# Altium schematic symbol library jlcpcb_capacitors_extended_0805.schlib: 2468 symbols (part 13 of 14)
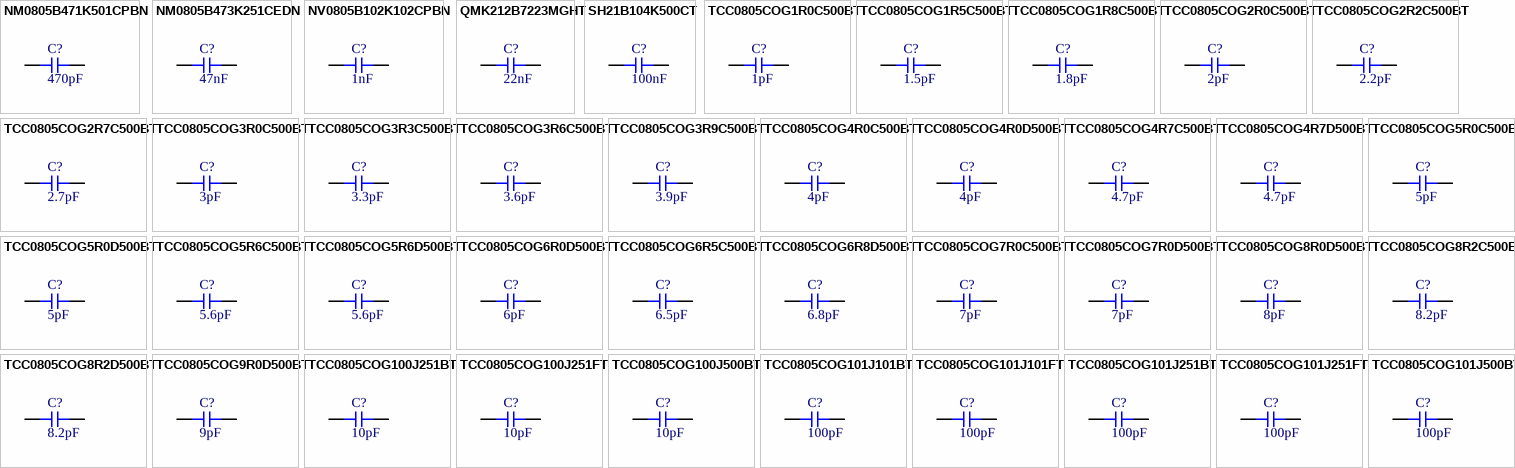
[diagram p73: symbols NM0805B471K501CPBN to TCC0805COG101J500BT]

## TCC0805COG9R0D500BT
designator C?  Capacitance: 9pF  (hidden comment: *)
Capacitor, Ceramic (MLCC), 9pF, ±0.5pF, 50V, C0G, ±0.5pF, SMD 0805; Manufacturer: CCTC; Manufacturer Part Number: TCC0805COG9R0D500BT
footprint CAP-0805 (0805 (2012M) Capacitor)
pins: 1, 2

## TCC0805COG100J251BT
designator C?  Capacitance: 10pF  (hidden comment: *)
Capacitor, Ceramic (MLCC), 10pF, ±5%, 250V, C0G, ±5%, SMD 0805; Manufacturer: CCTC; Manufacturer Part Number: TCC0805COG100J251BT
footprint CAP-0805 (0805 (2012M) Capacitor)
pins: 1, 2

## TCC0805COG100J251FT
designator C?  Capacitance: 10pF  (hidden comment: *)
Capacitor, Ceramic (MLCC), 10pF, ±5%, 250V, C0G, ±5%, SMD 0805; Manufacturer: CCTC; Manufacturer Part Number: TCC0805COG100J251FT
footprint CAP-0805 (0805 (2012M) Capacitor)
pins: 1, 2

## TCC0805COG100J500BT
designator C?  Capacitance: 10pF  (hidden comment: *)
Capacitor, Ceramic (MLCC), 10pF, ±5%, 50V, C0G, ±5%, SMD 0805; Manufacturer: CCTC; Manufacturer Part Number: TCC0805COG100J500BT
footprint CAP-0805 (0805 (2012M) Capacitor)
pins: 1, 2

## TCC0805COG101J101BT
designator C?  Capacitance: 100pF  (hidden comment: *)
Capacitor, Ceramic (MLCC), 100pF, ±5%, 100V, C0G, ±5%, SMD 0805; Manufacturer: CCTC; Manufacturer Part Number: TCC0805COG101J101BT
footprint CAP-0805 (0805 (2012M) Capacitor)
pins: 1, 2

## TCC0805COG101J101FT
designator C?  Capacitance: 100pF  (hidden comment: *)
Capacitor, Ceramic (MLCC), 100pF, ±5%, 100V, C0G, ±5%, SMD 0805; Manufacturer: CCTC; Manufacturer Part Number: TCC0805COG101J101FT
footprint CAP-0805 (0805 (2012M) Capacitor)
pins: 1, 2

## TCC0805COG101J251BT
designator C?  Capacitance: 100pF  (hidden comment: *)
Capacitor, Ceramic (MLCC), 100pF, ±5%, 250V, C0G, ±5%, SMD 0805; Manufacturer: CCTC; Manufacturer Part Number: TCC0805COG101J251BT
footprint CAP-0805 (0805 (2012M) Capacitor)
pins: 1, 2

## TCC0805COG101J251FT
designator C?  Capacitance: 100pF  (hidden comment: *)
Capacitor, Ceramic (MLCC), 100pF, ±5%, 250V, C0G, ±5%, SMD 0805; Manufacturer: CCTC; Manufacturer Part Number: TCC0805COG101J251FT
footprint CAP-0805 (0805 (2012M) Capacitor)
pins: 1, 2

## TCC0805COG101J500BT
designator C?  Capacitance: 100pF  (hidden comment: *)
Capacitor, Ceramic (MLCC), 100pF, ±5%, 50V, C0G, ±5%, SMD 0805; Manufacturer: CCTC; Manufacturer Part Number: TCC0805COG101J500BT
footprint CAP-0805 (0805 (2012M) Capacitor)
pins: 1, 2

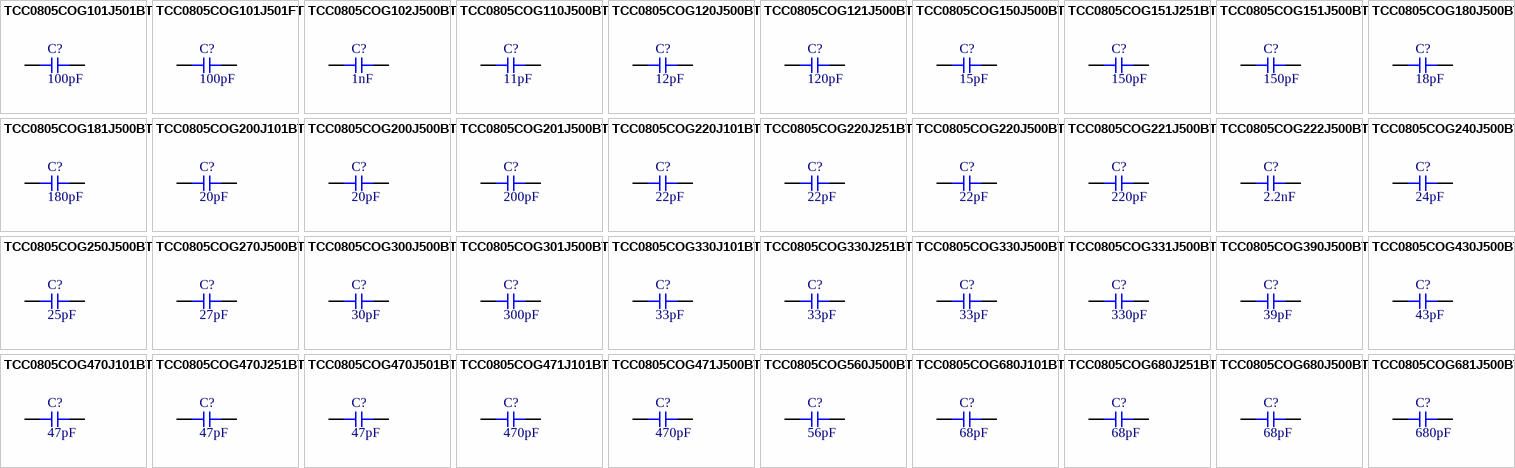
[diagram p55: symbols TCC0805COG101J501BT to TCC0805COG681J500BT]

## TCC0805COG101J501BT
designator C?  Capacitance: 100pF  (hidden comment: *)
Capacitor, Ceramic (MLCC), 100pF, ±5%, 500V, C0G, ±5%, SMD 0805; Manufacturer: CCTC; Manufacturer Part Number: TCC0805COG101J501BT
footprint CAP-0805 (0805 (2012M) Capacitor)
pins: 1, 2

## TCC0805COG101J501FT
designator C?  Capacitance: 100pF  (hidden comment: *)
Capacitor, Ceramic (MLCC), 100pF, ±5%, 500V, C0G, ±5%, SMD 0805; Manufacturer: CCTC; Manufacturer Part Number: TCC0805COG101J501FT
footprint CAP-0805 (0805 (2012M) Capacitor)
pins: 1, 2

## TCC0805COG102J500BT
designator C?  Capacitance: 1nF  (hidden comment: *)
Capacitor, Ceramic (MLCC), 1nF, ±5%, 50V, C0G, ±5%, SMD 0805; Manufacturer: CCTC; Manufacturer Part Number: TCC0805COG102J500BT
footprint CAP-0805 (0805 (2012M) Capacitor)
pins: 1, 2

## TCC0805COG110J500BT
designator C?  Capacitance: 11pF  (hidden comment: *)
Capacitor, Ceramic (MLCC), 11pF, ±5%, 50V, C0G, ±5%, SMD 0805; Manufacturer: CCTC; Manufacturer Part Number: TCC0805COG110J500BT
footprint CAP-0805 (0805 (2012M) Capacitor)
pins: 1, 2

## TCC0805COG120J500BT
designator C?  Capacitance: 12pF  (hidden comment: *)
Capacitor, Ceramic (MLCC), 12pF, ±5%, 50V, C0G, ±5%, SMD 0805; Manufacturer: CCTC; Manufacturer Part Number: TCC0805COG120J500BT
footprint CAP-0805 (0805 (2012M) Capacitor)
pins: 1, 2

## TCC0805COG121J500BT
designator C?  Capacitance: 120pF  (hidden comment: *)
Capacitor, Ceramic (MLCC), 120pF, ±5%, 50V, C0G, ±5%, SMD 0805; Manufacturer: CCTC; Manufacturer Part Number: TCC0805COG121J500BT
footprint CAP-0805 (0805 (2012M) Capacitor)
pins: 1, 2

## TCC0805COG150J500BT
designator C?  Capacitance: 15pF  (hidden comment: *)
Capacitor, Ceramic (MLCC), 15pF, ±5%, 50V, C0G, ±5%, SMD 0805; Manufacturer: CCTC; Manufacturer Part Number: TCC0805COG150J500BT
footprint CAP-0805 (0805 (2012M) Capacitor)
pins: 1, 2

## TCC0805COG151J251BT
designator C?  Capacitance: 150pF  (hidden comment: *)
Capacitor, Ceramic (MLCC), 150pF, ±5%, 250V, C0G, ±5%, SMD 0805; Manufacturer: CCTC; Manufacturer Part Number: TCC0805COG151J251BT
footprint CAP-0805 (0805 (2012M) Capacitor)
pins: 1, 2

## TCC0805COG151J500BT
designator C?  Capacitance: 150pF  (hidden comment: *)
Capacitor, Ceramic (MLCC), 150pF, ±5%, 50V, C0G, ±5%, SMD 0805; Manufacturer: CCTC; Manufacturer Part Number: TCC0805COG151J500BT
footprint CAP-0805 (0805 (2012M) Capacitor)
pins: 1, 2

## TCC0805COG180J500BT
designator C?  Capacitance: 18pF  (hidden comment: *)
Capacitor, Ceramic (MLCC), 18pF, ±5%, 50V, C0G, ±5%, SMD 0805; Manufacturer: CCTC; Manufacturer Part Number: TCC0805COG180J500BT
footprint CAP-0805 (0805 (2012M) Capacitor)
pins: 1, 2

## TCC0805COG181J500BT
designator C?  Capacitance: 180pF  (hidden comment: *)
Capacitor, Ceramic (MLCC), 180pF, ±5%, 50V, C0G, ±5%, SMD 0805; Manufacturer: CCTC; Manufacturer Part Number: TCC0805COG181J500BT
footprint CAP-0805 (0805 (2012M) Capacitor)
pins: 1, 2

## TCC0805COG200J101BT
designator C?  Capacitance: 20pF  (hidden comment: *)
Capacitor, Ceramic (MLCC), 20pF, ±5%, 100V, C0G, ±5%, SMD 0805; Manufacturer: CCTC; Manufacturer Part Number: TCC0805COG200J101BT
footprint CAP-0805 (0805 (2012M) Capacitor)
pins: 1, 2

## TCC0805COG200J500BT
designator C?  Capacitance: 20pF  (hidden comment: *)
Capacitor, Ceramic (MLCC), 20pF, ±5%, 50V, C0G, ±5%, SMD 0805; Manufacturer: CCTC; Manufacturer Part Number: TCC0805COG200J500BT
footprint CAP-0805 (0805 (2012M) Capacitor)
pins: 1, 2

## TCC0805COG201J500BT
designator C?  Capacitance: 200pF  (hidden comment: *)
Capacitor, Ceramic (MLCC), 200pF, ±5%, 50V, C0G, ±5%, SMD 0805; Manufacturer: CCTC; Manufacturer Part Number: TCC0805COG201J500BT
footprint CAP-0805 (0805 (2012M) Capacitor)
pins: 1, 2

## TCC0805COG220J101BT
designator C?  Capacitance: 22pF  (hidden comment: *)
Capacitor, Ceramic (MLCC), 22pF, ±5%, 100V, C0G, ±5%, SMD 0805; Manufacturer: CCTC; Manufacturer Part Number: TCC0805COG220J101BT
footprint CAP-0805 (0805 (2012M) Capacitor)
pins: 1, 2

## TCC0805COG220J251BT
designator C?  Capacitance: 22pF  (hidden comment: *)
Capacitor, Ceramic (MLCC), 22pF, ±5%, 250V, C0G, ±5%, SMD 0805; Manufacturer: CCTC; Manufacturer Part Number: TCC0805COG220J251BT
footprint CAP-0805 (0805 (2012M) Capacitor)
pins: 1, 2

## TCC0805COG220J500BT
designator C?  Capacitance: 22pF  (hidden comment: *)
Capacitor, Ceramic (MLCC), 22pF, ±5%, 50V, C0G, ±5%, SMD 0805; Manufacturer: CCTC; Manufacturer Part Number: TCC0805COG220J500BT
footprint CAP-0805 (0805 (2012M) Capacitor)
pins: 1, 2

## TCC0805COG221J500BT
designator C?  Capacitance: 220pF  (hidden comment: *)
Capacitor, Ceramic (MLCC), 220pF, ±5%, 50V, C0G, ±5%, SMD 0805; Manufacturer: CCTC; Manufacturer Part Number: TCC0805COG221J500BT
footprint CAP-0805 (0805 (2012M) Capacitor)
pins: 1, 2

## TCC0805COG222J500BT
designator C?  Capacitance: 2.2nF  (hidden comment: *)
Capacitor, Ceramic (MLCC), 2.2nF, ±5%, 50V, C0G, ±5%, SMD 0805; Manufacturer: CCTC; Manufacturer Part Number: TCC0805COG222J500BT
footprint CAP-0805 (0805 (2012M) Capacitor)
pins: 1, 2

## TCC0805COG240J500BT
designator C?  Capacitance: 24pF  (hidden comment: *)
Capacitor, Ceramic (MLCC), 24pF, ±5%, 50V, C0G, ±5%, SMD 0805; Manufacturer: CCTC; Manufacturer Part Number: TCC0805COG240J500BT
footprint CAP-0805 (0805 (2012M) Capacitor)
pins: 1, 2

## TCC0805COG250J500BT
designator C?  Capacitance: 25pF  (hidden comment: *)
Capacitor, Ceramic (MLCC), 25pF, ±5%, 50V, C0G, ±5%, SMD 0805; Manufacturer: CCTC; Manufacturer Part Number: TCC0805COG250J500BT
footprint CAP-0805 (0805 (2012M) Capacitor)
pins: 1, 2

## TCC0805COG270J500BT
designator C?  Capacitance: 27pF  (hidden comment: *)
Capacitor, Ceramic (MLCC), 27pF, ±5%, 50V, C0G, ±5%, SMD 0805; Manufacturer: CCTC; Manufacturer Part Number: TCC0805COG270J500BT
footprint CAP-0805 (0805 (2012M) Capacitor)
pins: 1, 2

## TCC0805COG300J500BT
designator C?  Capacitance: 30pF  (hidden comment: *)
Capacitor, Ceramic (MLCC), 30pF, ±5%, 50V, C0G, ±5%, SMD 0805; Manufacturer: CCTC; Manufacturer Part Number: TCC0805COG300J500BT
footprint CAP-0805 (0805 (2012M) Capacitor)
pins: 1, 2

## TCC0805COG301J500BT
designator C?  Capacitance: 300pF  (hidden comment: *)
Capacitor, Ceramic (MLCC), 300pF, ±5%, 50V, C0G, ±5%, SMD 0805; Manufacturer: CCTC; Manufacturer Part Number: TCC0805COG301J500BT
footprint CAP-0805 (0805 (2012M) Capacitor)
pins: 1, 2

## TCC0805COG330J101BT
designator C?  Capacitance: 33pF  (hidden comment: *)
Capacitor, Ceramic (MLCC), 33pF, ±5%, 100V, C0G, ±5%, SMD 0805; Manufacturer: CCTC; Manufacturer Part Number: TCC0805COG330J101BT
footprint CAP-0805 (0805 (2012M) Capacitor)
pins: 1, 2

## TCC0805COG330J251BT
designator C?  Capacitance: 33pF  (hidden comment: *)
Capacitor, Ceramic (MLCC), 33pF, ±5%, 250V, C0G, ±5%, SMD 0805; Manufacturer: CCTC; Manufacturer Part Number: TCC0805COG330J251BT
footprint CAP-0805 (0805 (2012M) Capacitor)
pins: 1, 2

## TCC0805COG330J500BT
designator C?  Capacitance: 33pF  (hidden comment: *)
Capacitor, Ceramic (MLCC), 33pF, ±5%, 50V, C0G, ±5%, SMD 0805; Manufacturer: CCTC; Manufacturer Part Number: TCC0805COG330J500BT
footprint CAP-0805 (0805 (2012M) Capacitor)
pins: 1, 2

## TCC0805COG331J500BT
designator C?  Capacitance: 330pF  (hidden comment: *)
Capacitor, Ceramic (MLCC), 330pF, ±5%, 50V, C0G, ±5%, SMD 0805; Manufacturer: CCTC; Manufacturer Part Number: TCC0805COG331J500BT
footprint CAP-0805 (0805 (2012M) Capacitor)
pins: 1, 2

## TCC0805COG390J500BT
designator C?  Capacitance: 39pF  (hidden comment: *)
Capacitor, Ceramic (MLCC), 39pF, ±5%, 50V, C0G, ±5%, SMD 0805; Manufacturer: CCTC; Manufacturer Part Number: TCC0805COG390J500BT
footprint CAP-0805 (0805 (2012M) Capacitor)
pins: 1, 2

## TCC0805COG430J500BT
designator C?  Capacitance: 43pF  (hidden comment: *)
Capacitor, Ceramic (MLCC), 43pF, ±5%, 50V, C0G, ±5%, SMD 0805; Manufacturer: CCTC; Manufacturer Part Number: TCC0805COG430J500BT
footprint CAP-0805 (0805 (2012M) Capacitor)
pins: 1, 2

## TCC0805COG470J101BT
designator C?  Capacitance: 47pF  (hidden comment: *)
Capacitor, Ceramic (MLCC), 47pF, ±5%, 100V, C0G, ±5%, SMD 0805; Manufacturer: CCTC; Manufacturer Part Number: TCC0805COG470J101BT
footprint CAP-0805 (0805 (2012M) Capacitor)
pins: 1, 2

## TCC0805COG470J251BT
designator C?  Capacitance: 47pF  (hidden comment: *)
Capacitor, Ceramic (MLCC), 47pF, ±5%, 250V, C0G, ±5%, SMD 0805; Manufacturer: CCTC; Manufacturer Part Number: TCC0805COG470J251BT
footprint CAP-0805 (0805 (2012M) Capacitor)
pins: 1, 2

## TCC0805COG470J501BT
designator C?  Capacitance: 47pF  (hidden comment: *)
Capacitor, Ceramic (MLCC), 47pF, ±5%, 500V, C0G, ±5%, SMD 0805; Manufacturer: CCTC; Manufacturer Part Number: TCC0805COG470J501BT
footprint CAP-0805 (0805 (2012M) Capacitor)
pins: 1, 2

## TCC0805COG471J101BT
designator C?  Capacitance: 470pF  (hidden comment: *)
Capacitor, Ceramic (MLCC), 470pF, ±5%, 100V, C0G, ±5%, SMD 0805; Manufacturer: CCTC; Manufacturer Part Number: TCC0805COG471J101BT
footprint CAP-0805 (0805 (2012M) Capacitor)
pins: 1, 2

## TCC0805COG471J500BT
designator C?  Capacitance: 470pF  (hidden comment: *)
Capacitor, Ceramic (MLCC), 470pF, ±5%, 50V, C0G, ±5%, SMD 0805; Manufacturer: CCTC; Manufacturer Part Number: TCC0805COG471J500BT
footprint CAP-0805 (0805 (2012M) Capacitor)
pins: 1, 2

## TCC0805COG560J500BT
designator C?  Capacitance: 56pF  (hidden comment: *)
Capacitor, Ceramic (MLCC), 56pF, ±5%, 50V, C0G, ±5%, SMD 0805; Manufacturer: CCTC; Manufacturer Part Number: TCC0805COG560J500BT
footprint CAP-0805 (0805 (2012M) Capacitor)
pins: 1, 2

## TCC0805COG680J101BT
designator C?  Capacitance: 68pF  (hidden comment: *)
Capacitor, Ceramic (MLCC), 68pF, ±5%, 100V, C0G, ±5%, SMD 0805; Manufacturer: CCTC; Manufacturer Part Number: TCC0805COG680J101BT
footprint CAP-0805 (0805 (2012M) Capacitor)
pins: 1, 2

## TCC0805COG680J251BT
designator C?  Capacitance: 68pF  (hidden comment: *)
Capacitor, Ceramic (MLCC), 68pF, ±5%, 250V, C0G, ±5%, SMD 0805; Manufacturer: CCTC; Manufacturer Part Number: TCC0805COG680J251BT
footprint CAP-0805 (0805 (2012M) Capacitor)
pins: 1, 2

## TCC0805COG680J500BT
designator C?  Capacitance: 68pF  (hidden comment: *)
Capacitor, Ceramic (MLCC), 68pF, ±5%, 50V, C0G, ±5%, SMD 0805; Manufacturer: CCTC; Manufacturer Part Number: TCC0805COG680J500BT
footprint CAP-0805 (0805 (2012M) Capacitor)
pins: 1, 2

## TCC0805COG681J500BT
designator C?  Capacitance: 680pF  (hidden comment: *)
Capacitor, Ceramic (MLCC), 680pF, ±5%, 50V, C0G, ±5%, SMD 0805; Manufacturer: CCTC; Manufacturer Part Number: TCC0805COG681J500BT
footprint CAP-0805 (0805 (2012M) Capacitor)
pins: 1, 2

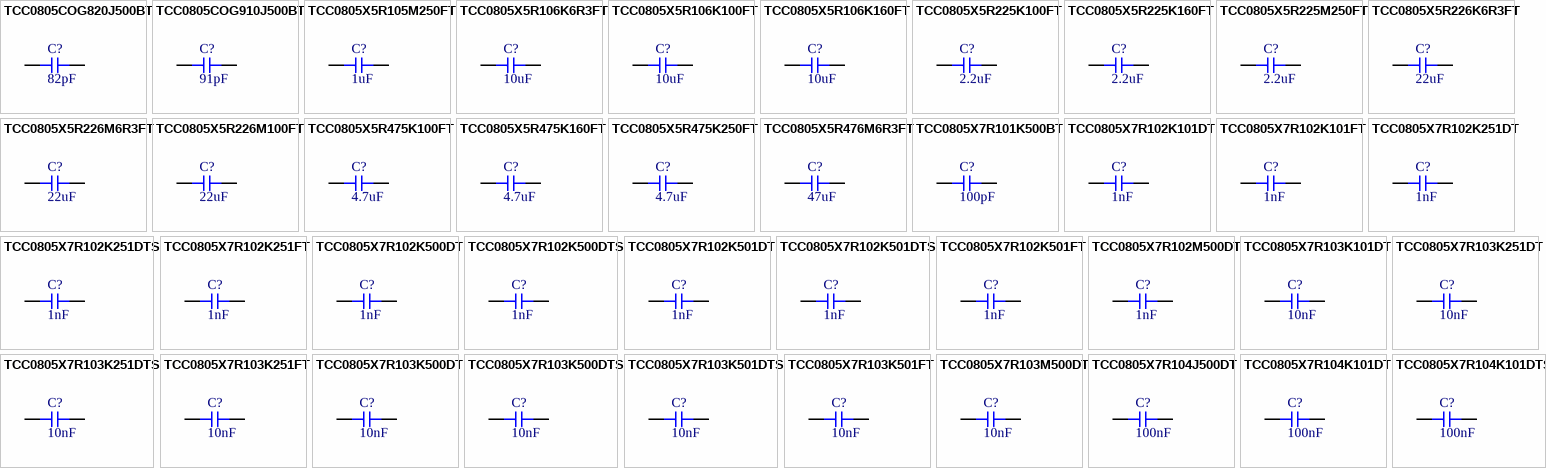
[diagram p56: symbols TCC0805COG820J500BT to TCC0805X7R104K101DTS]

## TCC0805COG820J500BT
designator C?  Capacitance: 82pF  (hidden comment: *)
Capacitor, Ceramic (MLCC), 82pF, ±5%, 50V, C0G, ±5%, SMD 0805; Manufacturer: CCTC; Manufacturer Part Number: TCC0805COG820J500BT
footprint CAP-0805 (0805 (2012M) Capacitor)
pins: 1, 2

## TCC0805COG910J500BT
designator C?  Capacitance: 91pF  (hidden comment: *)
Capacitor, Ceramic (MLCC), 91pF, ±5%, 50V, C0G, ±5%, SMD 0805; Manufacturer: CCTC; Manufacturer Part Number: TCC0805COG910J500BT
footprint CAP-0805 (0805 (2012M) Capacitor)
pins: 1, 2

## TCC0805X5R105M250FT
designator C?  Capacitance: 1uF  (hidden comment: *)
Capacitor, Ceramic (MLCC), 1uF, ±20%, 25V, X5R, ±20%, SMD 0805; Manufacturer: CCTC; Manufacturer Part Number: TCC0805X5R105M250FT
footprint CAP-0805 (0805 (2012M) Capacitor)
pins: 1, 2

## TCC0805X5R106K6R3FT
designator C?  Capacitance: 10uF  (hidden comment: *)
Capacitor, Ceramic (MLCC), 10uF, ±10%, 6.3V, X5R, ±10%, SMD 0805; Manufacturer: CCTC; Manufacturer Part Number: TCC0805X5R106K6R3FT
footprint CAP-0805 (0805 (2012M) Capacitor)
pins: 1, 2

## TCC0805X5R106K100FT
designator C?  Capacitance: 10uF  (hidden comment: *)
Capacitor, Ceramic (MLCC), 10uF, ±10%, 10V, X5R, ±10%, SMD 0805; Manufacturer: CCTC; Manufacturer Part Number: TCC0805X5R106K100FT
footprint CAP-0805 (0805 (2012M) Capacitor)
pins: 1, 2

## TCC0805X5R106K160FT
designator C?  Capacitance: 10uF  (hidden comment: *)
Capacitor, Ceramic (MLCC), 10uF, ±10%, 16V, X5R, ±10%, SMD 0805; Manufacturer: CCTC; Manufacturer Part Number: TCC0805X5R106K160FT
footprint CAP-0805 (0805 (2012M) Capacitor)
pins: 1, 2

## TCC0805X5R225K100FT
designator C?  Capacitance: 2.2uF  (hidden comment: *)
Capacitor, Ceramic (MLCC), 2.2uF, ±10%, 10V, X5R, ±10%, SMD 0805; Manufacturer: CCTC; Manufacturer Part Number: TCC0805X5R225K100FT
footprint CAP-0805 (0805 (2012M) Capacitor)
pins: 1, 2

## TCC0805X5R225K160FT
designator C?  Capacitance: 2.2uF  (hidden comment: *)
Capacitor, Ceramic (MLCC), 2.2uF, ±10%, 16V, X5R, ±10%, SMD 0805; Manufacturer: CCTC; Manufacturer Part Number: TCC0805X5R225K160FT
footprint CAP-0805 (0805 (2012M) Capacitor)
pins: 1, 2

## TCC0805X5R225M250FT
designator C?  Capacitance: 2.2uF  (hidden comment: *)
Capacitor, Ceramic (MLCC), 2.2uF, ±20%, 25V, X5R, ±20%, SMD 0805; Manufacturer: CCTC; Manufacturer Part Number: TCC0805X5R225M250FT
footprint CAP-0805 (0805 (2012M) Capacitor)
pins: 1, 2

## TCC0805X5R226K6R3FT
designator C?  Capacitance: 22uF  (hidden comment: *)
Capacitor, Ceramic (MLCC), 22uF, ±10%, 6.3V, X5R, ±10%, SMD 0805; Manufacturer: CCTC; Manufacturer Part Number: TCC0805X5R226K6R3FT
footprint CAP-0805 (0805 (2012M) Capacitor)
pins: 1, 2

## TCC0805X5R226M6R3FT
designator C?  Capacitance: 22uF  (hidden comment: *)
Capacitor, Ceramic (MLCC), 22uF, ±20%, 6.3V, X5R, ±20%, SMD 0805; Manufacturer: CCTC; Manufacturer Part Number: TCC0805X5R226M6R3FT
footprint CAP-0805 (0805 (2012M) Capacitor)
pins: 1, 2

## TCC0805X5R226M100FT
designator C?  Capacitance: 22uF  (hidden comment: *)
Capacitor, Ceramic (MLCC), 22uF, ±20%, 10V, X5R, ±20%, SMD 0805; Manufacturer: CCTC; Manufacturer Part Number: TCC0805X5R226M100FT
footprint CAP-0805 (0805 (2012M) Capacitor)
pins: 1, 2

## TCC0805X5R475K100FT
designator C?  Capacitance: 4.7uF  (hidden comment: *)
Capacitor, Ceramic (MLCC), 4.7uF, ±10%, 10V, X5R, ±10%, SMD 0805; Manufacturer: CCTC; Manufacturer Part Number: TCC0805X5R475K100FT
footprint CAP-0805 (0805 (2012M) Capacitor)
pins: 1, 2

## TCC0805X5R475K160FT
designator C?  Capacitance: 4.7uF  (hidden comment: *)
Capacitor, Ceramic (MLCC), 4.7uF, ±10%, 16V, X5R, ±10%, SMD 0805; Manufacturer: CCTC; Manufacturer Part Number: TCC0805X5R475K160FT
footprint CAP-0805 (0805 (2012M) Capacitor)
pins: 1, 2

## TCC0805X5R475K250FT
designator C?  Capacitance: 4.7uF  (hidden comment: *)
Capacitor, Ceramic (MLCC), 4.7uF, ±10%, 25V, X5R, ±10%, SMD 0805; Manufacturer: CCTC; Manufacturer Part Number: TCC0805X5R475K250FT
footprint CAP-0805 (0805 (2012M) Capacitor)
pins: 1, 2

## TCC0805X5R476M6R3FT
designator C?  Capacitance: 47uF  (hidden comment: *)
Capacitor, Ceramic (MLCC), 47uF, ±20%, 6.3V, X5R, ±20%, SMD 0805; Manufacturer: CCTC; Manufacturer Part Number: TCC0805X5R476M6R3FT
footprint CAP-0805 (0805 (2012M) Capacitor)
pins: 1, 2

## TCC0805X7R101K500BT
designator C?  Capacitance: 100pF  (hidden comment: *)
Capacitor, Ceramic (MLCC), 100pF, ±10%, 50V, X7R, ±10%, SMD 0805; Manufacturer: CCTC; Manufacturer Part Number: TCC0805X7R101K500BT
footprint CAP-0805 (0805 (2012M) Capacitor)
pins: 1, 2

## TCC0805X7R102K101DT
designator C?  Capacitance: 1nF  (hidden comment: *)
Capacitor, Ceramic (MLCC), 1nF, ±10%, 100V, X7R, ±10%, SMD 0805; Manufacturer: CCTC; Manufacturer Part Number: TCC0805X7R102K101DT
footprint CAP-0805 (0805 (2012M) Capacitor)
pins: 1, 2

## TCC0805X7R102K101FT
designator C?  Capacitance: 1nF  (hidden comment: *)
Capacitor, Ceramic (MLCC), 1nF, ±10%, 100V, X7R, ±10%, SMD 0805; Manufacturer: CCTC; Manufacturer Part Number: TCC0805X7R102K101FT
footprint CAP-0805 (0805 (2012M) Capacitor)
pins: 1, 2

## TCC0805X7R102K251DT
designator C?  Capacitance: 1nF  (hidden comment: *)
Capacitor, Ceramic (MLCC), 1nF, ±10%, 250V, X7R, ±10%, SMD 0805; Manufacturer: CCTC; Manufacturer Part Number: TCC0805X7R102K251DT
footprint CAP-0805 (0805 (2012M) Capacitor)
pins: 1, 2

## TCC0805X7R102K251DTS
designator C?  Capacitance: 1nF  (hidden comment: *)
Capacitor, Ceramic (MLCC), 1nF, ±10%, 250V, X7R, ±10%, SMD 0805; Manufacturer: CCTC; Manufacturer Part Number: TCC0805X7R102K251DTS
footprint CAP-0805 (0805 (2012M) Capacitor)
pins: 1, 2

## TCC0805X7R102K251FT
designator C?  Capacitance: 1nF  (hidden comment: *)
Capacitor, Ceramic (MLCC), 1nF, ±10%, 250V, X7R, ±10%, SMD 0805; Manufacturer: CCTC; Manufacturer Part Number: TCC0805X7R102K251FT
footprint CAP-0805 (0805 (2012M) Capacitor)
pins: 1, 2

## TCC0805X7R102K500DT
designator C?  Capacitance: 1nF  (hidden comment: *)
Capacitor, Ceramic (MLCC), 1nF, ±10%, 50V, X7R, ±10%, SMD 0805; Manufacturer: CCTC; Manufacturer Part Number: TCC0805X7R102K500DT
footprint CAP-0805 (0805 (2012M) Capacitor)
pins: 1, 2

## TCC0805X7R102K500DTS
designator C?  Capacitance: 1nF  (hidden comment: *)
Capacitor, Ceramic (MLCC), 1nF, ±10%, 50V, X7R, ±10%, SMD 0805; Manufacturer: CCTC; Manufacturer Part Number: TCC0805X7R102K500DTS
footprint CAP-0805 (0805 (2012M) Capacitor)
pins: 1, 2

## TCC0805X7R102K501DT
designator C?  Capacitance: 1nF  (hidden comment: *)
Capacitor, Ceramic (MLCC), 1nF, ±10%, 500V, X7R, ±10%, SMD 0805; Manufacturer: CCTC; Manufacturer Part Number: TCC0805X7R102K501DT
footprint CAP-0805 (0805 (2012M) Capacitor)
pins: 1, 2

## TCC0805X7R102K501DTS
designator C?  Capacitance: 1nF  (hidden comment: *)
Capacitor, Ceramic (MLCC), 1nF, ±10%, 500V, X7R, ±10%, SMD 0805; Manufacturer: CCTC; Manufacturer Part Number: TCC0805X7R102K501DTS
footprint CAP-0805 (0805 (2012M) Capacitor)
pins: 1, 2

## TCC0805X7R102K501FT
designator C?  Capacitance: 1nF  (hidden comment: *)
Capacitor, Ceramic (MLCC), 1nF, ±10%, 500V, X7R, ±10%, SMD 0805; Manufacturer: CCTC; Manufacturer Part Number: TCC0805X7R102K501FT
footprint CAP-0805 (0805 (2012M) Capacitor)
pins: 1, 2

## TCC0805X7R102M500DT
designator C?  Capacitance: 1nF  (hidden comment: *)
Capacitor, Ceramic (MLCC), 1nF, ±20%, 50V, X7R, ±20%, SMD 0805; Manufacturer: CCTC; Manufacturer Part Number: TCC0805X7R102M500DT
footprint CAP-0805 (0805 (2012M) Capacitor)
pins: 1, 2

## TCC0805X7R103K101DT
designator C?  Capacitance: 10nF  (hidden comment: *)
Capacitor, Ceramic (MLCC), 10nF, ±10%, 100V, X7R, ±10%, SMD 0805; Manufacturer: CCTC; Manufacturer Part Number: TCC0805X7R103K101DT
footprint CAP-0805 (0805 (2012M) Capacitor)
pins: 1, 2

## TCC0805X7R103K251DT
designator C?  Capacitance: 10nF  (hidden comment: *)
Capacitor, Ceramic (MLCC), 10nF, ±10%, 250V, X7R, ±10%, SMD 0805; Manufacturer: CCTC; Manufacturer Part Number: TCC0805X7R103K251DT
footprint CAP-0805 (0805 (2012M) Capacitor)
pins: 1, 2

## TCC0805X7R103K251DTS
designator C?  Capacitance: 10nF  (hidden comment: *)
Capacitor, Ceramic (MLCC), 10nF, ±10%, 250V, X7R, ±10%, SMD 0805; Manufacturer: CCTC; Manufacturer Part Number: TCC0805X7R103K251DTS
footprint CAP-0805 (0805 (2012M) Capacitor)
pins: 1, 2

## TCC0805X7R103K251FT
designator C?  Capacitance: 10nF  (hidden comment: *)
Capacitor, Ceramic (MLCC), 10nF, ±10%, 250V, X7R, ±10%, SMD 0805; Manufacturer: CCTC; Manufacturer Part Number: TCC0805X7R103K251FT
footprint CAP-0805 (0805 (2012M) Capacitor)
pins: 1, 2

## TCC0805X7R103K500DT
designator C?  Capacitance: 10nF  (hidden comment: *)
Capacitor, Ceramic (MLCC), 10nF, ±10%, 50V, X7R, ±10%, SMD 0805; Manufacturer: CCTC; Manufacturer Part Number: TCC0805X7R103K500DT
footprint CAP-0805 (0805 (2012M) Capacitor)
pins: 1, 2

## TCC0805X7R103K500DTS
designator C?  Capacitance: 10nF  (hidden comment: *)
Capacitor, Ceramic (MLCC), 10nF, ±10%, 50V, X7R, ±10%, SMD 0805; Manufacturer: CCTC; Manufacturer Part Number: TCC0805X7R103K500DTS
footprint CAP-0805 (0805 (2012M) Capacitor)
pins: 1, 2

## TCC0805X7R103K501DTS
designator C?  Capacitance: 10nF  (hidden comment: *)
Capacitor, Ceramic (MLCC), 10nF, ±10%, 500V, X7R, ±10%, SMD 0805; Manufacturer: CCTC; Manufacturer Part Number: TCC0805X7R103K501DTS
footprint CAP-0805 (0805 (2012M) Capacitor)
pins: 1, 2

## TCC0805X7R103K501FT
designator C?  Capacitance: 10nF  (hidden comment: *)
Capacitor, Ceramic (MLCC), 10nF, ±10%, 500V, X7R, ±10%, SMD 0805; Manufacturer: CCTC; Manufacturer Part Number: TCC0805X7R103K501FT
footprint CAP-0805 (0805 (2012M) Capacitor)
pins: 1, 2

## TCC0805X7R103M500DT
designator C?  Capacitance: 10nF  (hidden comment: *)
Capacitor, Ceramic (MLCC), 10nF, ±20%, 50V, X7R, ±20%, SMD 0805; Manufacturer: CCTC; Manufacturer Part Number: TCC0805X7R103M500DT
footprint CAP-0805 (0805 (2012M) Capacitor)
pins: 1, 2

## TCC0805X7R104J500DT
designator C?  Capacitance: 100nF  (hidden comment: *)
Capacitor, Ceramic (MLCC), 100nF, ±5%, 50V, X7R, ±5%, SMD 0805; Manufacturer: CCTC; Manufacturer Part Number: TCC0805X7R104J500DT
footprint CAP-0805 (0805 (2012M) Capacitor)
pins: 1, 2

## TCC0805X7R104K101DT
designator C?  Capacitance: 100nF  (hidden comment: *)
Capacitor, Ceramic (MLCC), 100nF, ±10%, 100V, X7R, ±10%, SMD 0805; Manufacturer: CCTC; Manufacturer Part Number: TCC0805X7R104K101DT
footprint CAP-0805 (0805 (2012M) Capacitor)
pins: 1, 2

## TCC0805X7R104K101DTS
designator C?  Capacitance: 100nF  (hidden comment: *)
Capacitor, Ceramic (MLCC), 100nF, ±10%, 100V, X7R, ±10%, SMD 0805; Manufacturer: CCTC; Manufacturer Part Number: TCC0805X7R104K101DTS
footprint CAP-0805 (0805 (2012M) Capacitor)
pins: 1, 2

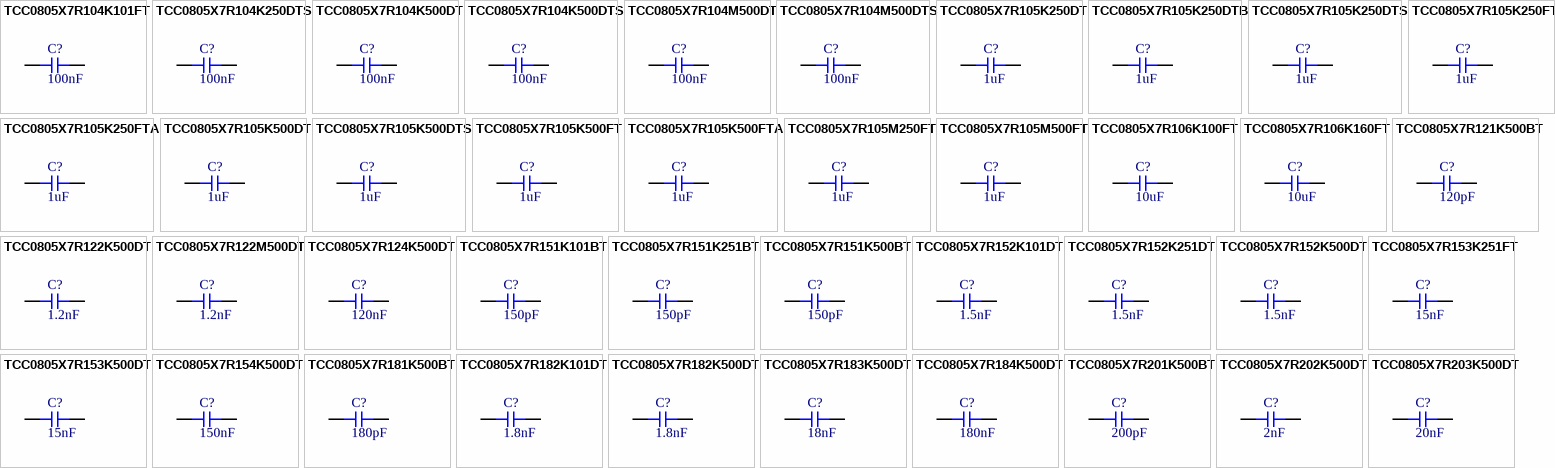
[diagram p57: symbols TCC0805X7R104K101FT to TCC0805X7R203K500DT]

## TCC0805X7R104K101FT
designator C?  Capacitance: 100nF  (hidden comment: *)
Capacitor, Ceramic (MLCC), 100nF, ±10%, 100V, X7R, ±10%, SMD 0805; Manufacturer: CCTC; Manufacturer Part Number: TCC0805X7R104K101FT
footprint CAP-0805 (0805 (2012M) Capacitor)
pins: 1, 2

## TCC0805X7R104K250DTS
designator C?  Capacitance: 100nF  (hidden comment: *)
Capacitor, Ceramic (MLCC), 100nF, ±10%, 25V, X7R, ±10%, SMD 0805; Manufacturer: CCTC; Manufacturer Part Number: TCC0805X7R104K250DTS
footprint CAP-0805 (0805 (2012M) Capacitor)
pins: 1, 2

## TCC0805X7R104K500DT
designator C?  Capacitance: 100nF  (hidden comment: *)
Capacitor, Ceramic (MLCC), 100nF, ±10%, 50V, X7R, ±10%, SMD 0805; Manufacturer: CCTC; Manufacturer Part Number: TCC0805X7R104K500DT
footprint CAP-0805 (0805 (2012M) Capacitor)
pins: 1, 2

## TCC0805X7R104K500DTS
designator C?  Capacitance: 100nF  (hidden comment: *)
Capacitor, Ceramic (MLCC), 100nF, ±10%, 50V, X7R, ±10%, SMD 0805; Manufacturer: CCTC; Manufacturer Part Number: TCC0805X7R104K500DTS
footprint CAP-0805 (0805 (2012M) Capacitor)
pins: 1, 2

## TCC0805X7R104M500DT
designator C?  Capacitance: 100nF  (hidden comment: *)
Capacitor, Ceramic (MLCC), 100nF, ±20%, 50V, X7R, ±20%, SMD 0805; Manufacturer: CCTC; Manufacturer Part Number: TCC0805X7R104M500DT
footprint CAP-0805 (0805 (2012M) Capacitor)
pins: 1, 2

## TCC0805X7R104M500DTS
designator C?  Capacitance: 100nF  (hidden comment: *)
Capacitor, Ceramic (MLCC), 100nF, ±20%, 50V, ±20%, SMD 0805; Manufacturer: CCTC; Manufacturer Part Number: TCC0805X7R104M500DTS
footprint CAP-0805 (0805 (2012M) Capacitor)
pins: 1, 2

## TCC0805X7R105K250DT
designator C?  Capacitance: 1uF  (hidden comment: *)
Capacitor, Ceramic (MLCC), 1uF, ±10%, 25V, X7R, ±10%, SMD 0805; Manufacturer: CCTC; Manufacturer Part Number: TCC0805X7R105K250DT
footprint CAP-0805 (0805 (2012M) Capacitor)
pins: 1, 2

## TCC0805X7R105K250DTB
designator C?  Capacitance: 1uF  (hidden comment: *)
Capacitor, Ceramic (MLCC), 1uF, ±10%, 25V, X7R, ±10%, SMD 0805; Manufacturer: CCTC; Manufacturer Part Number: TCC0805X7R105K250DTB
footprint CAP-0805 (0805 (2012M) Capacitor)
pins: 1, 2

## TCC0805X7R105K250DTS
designator C?  Capacitance: 1uF  (hidden comment: *)
Capacitor, Ceramic (MLCC), 1uF, ±10%, 25V, X7R, ±10%, SMD 0805; Manufacturer: CCTC; Manufacturer Part Number: TCC0805X7R105K250DTS
footprint CAP-0805 (0805 (2012M) Capacitor)
pins: 1, 2

## TCC0805X7R105K250FT
designator C?  Capacitance: 1uF  (hidden comment: *)
Capacitor, Ceramic (MLCC), 1uF, ±10%, 25V, X7R, ±10%, SMD 0805; Manufacturer: CCTC; Manufacturer Part Number: TCC0805X7R105K250FT
footprint CAP-0805 (0805 (2012M) Capacitor)
pins: 1, 2

## TCC0805X7R105K250FTA
designator C?  Capacitance: 1uF  (hidden comment: *)
Capacitor, Ceramic (MLCC), 1uF, ±10%, 25V, X7R, ±10%, SMD 0805; Manufacturer: CCTC; Manufacturer Part Number: TCC0805X7R105K250FTA
footprint CAP-0805 (0805 (2012M) Capacitor)
pins: 1, 2

## TCC0805X7R105K500DT
designator C?  Capacitance: 1uF  (hidden comment: *)
Capacitor, Ceramic (MLCC), 1uF, ±10%, 50V, X7R, ±10%, SMD 0805; Manufacturer: CCTC; Manufacturer Part Number: TCC0805X7R105K500DT
footprint CAP-0805 (0805 (2012M) Capacitor)
pins: 1, 2

## TCC0805X7R105K500DTS
designator C?  Capacitance: 1uF  (hidden comment: *)
Capacitor, Ceramic (MLCC), 1uF, ±10%, 50V, X7R, ±10%, SMD 0805; Manufacturer: CCTC; Manufacturer Part Number: TCC0805X7R105K500DTS
footprint CAP-0805 (0805 (2012M) Capacitor)
pins: 1, 2

## TCC0805X7R105K500FT
designator C?  Capacitance: 1uF  (hidden comment: *)
Capacitor, Ceramic (MLCC), 1uF, ±10%, 50V, X7R, ±10%, SMD 0805; Manufacturer: CCTC; Manufacturer Part Number: TCC0805X7R105K500FT
footprint CAP-0805 (0805 (2012M) Capacitor)
pins: 1, 2

## TCC0805X7R105K500FTA
designator C?  Capacitance: 1uF  (hidden comment: *)
Capacitor, Ceramic (MLCC), 1uF, ±10%, 50V, X7R, ±10%, SMD 0805; Manufacturer: CCTC; Manufacturer Part Number: TCC0805X7R105K500FTA
footprint CAP-0805 (0805 (2012M) Capacitor)
pins: 1, 2

## TCC0805X7R105M250FT
designator C?  Capacitance: 1uF  (hidden comment: *)
Capacitor, Ceramic (MLCC), 1uF, ±20%, 25V, X7R, ±20%, SMD 0805; Manufacturer: CCTC; Manufacturer Part Number: TCC0805X7R105M250FT
footprint CAP-0805 (0805 (2012M) Capacitor)
pins: 1, 2

## TCC0805X7R105M500FT
designator C?  Capacitance: 1uF  (hidden comment: *)
Capacitor, Ceramic (MLCC), 1uF, ±20%, 50V, X7R, ±20%, SMD 0805; Manufacturer: CCTC; Manufacturer Part Number: TCC0805X7R105M500FT
footprint CAP-0805 (0805 (2012M) Capacitor)
pins: 1, 2

## TCC0805X7R106K100FT
designator C?  Capacitance: 10uF  (hidden comment: *)
Capacitor, Ceramic (MLCC), 10uF, ±10%, 10V, X7R, ±10%, SMD 0805; Manufacturer: CCTC; Manufacturer Part Number: TCC0805X7R106K100FT
footprint CAP-0805 (0805 (2012M) Capacitor)
pins: 1, 2

## TCC0805X7R106K160FT
designator C?  Capacitance: 10uF  (hidden comment: *)
Capacitor, Ceramic (MLCC), 10uF, ±10%, 16V, X7R, ±10%, SMD 0805; Manufacturer: CCTC; Manufacturer Part Number: TCC0805X7R106K160FT
footprint CAP-0805 (0805 (2012M) Capacitor)
pins: 1, 2

## TCC0805X7R121K500BT
designator C?  Capacitance: 120pF  (hidden comment: *)
Capacitor, Ceramic (MLCC), 120pF, ±10%, 50V, X7R, ±10%, SMD 0805; Manufacturer: CCTC; Manufacturer Part Number: TCC0805X7R121K500BT
footprint CAP-0805 (0805 (2012M) Capacitor)
pins: 1, 2

## TCC0805X7R122K500DT
designator C?  Capacitance: 1.2nF  (hidden comment: *)
Capacitor, Ceramic (MLCC), 1.2nF, ±10%, 50V, X7R, ±10%, SMD 0805; Manufacturer: CCTC; Manufacturer Part Number: TCC0805X7R122K500DT
footprint CAP-0805 (0805 (2012M) Capacitor)
pins: 1, 2

## TCC0805X7R122M500DT
designator C?  Capacitance: 1.2nF  (hidden comment: *)
Capacitor, Ceramic (MLCC), 1.2nF, ±20%, 50V, ±20%, SMD 0805; Manufacturer: CCTC; Manufacturer Part Number: TCC0805X7R122M500DT
footprint CAP-0805 (0805 (2012M) Capacitor)
pins: 1, 2

## TCC0805X7R124K500DT
designator C?  Capacitance: 120nF  (hidden comment: *)
Capacitor, Ceramic (MLCC), 120nF, ±10%, 50V, X7R, ±10%, SMD 0805; Manufacturer: CCTC; Manufacturer Part Number: TCC0805X7R124K500DT
footprint CAP-0805 (0805 (2012M) Capacitor)
pins: 1, 2

## TCC0805X7R151K101BT
designator C?  Capacitance: 150pF  (hidden comment: *)
Capacitor, Ceramic (MLCC), 150pF, ±10%, 100V, X7R, ±10%, SMD 0805; Manufacturer: CCTC; Manufacturer Part Number: TCC0805X7R151K101BT
footprint CAP-0805 (0805 (2012M) Capacitor)
pins: 1, 2

## TCC0805X7R151K251BT
designator C?  Capacitance: 150pF  (hidden comment: *)
Capacitor, Ceramic (MLCC), 150pF, ±10%, 250V, X7R, ±10%, SMD 0805; Manufacturer: CCTC; Manufacturer Part Number: TCC0805X7R151K251BT
footprint CAP-0805 (0805 (2012M) Capacitor)
pins: 1, 2

## TCC0805X7R151K500BT
designator C?  Capacitance: 150pF  (hidden comment: *)
Capacitor, Ceramic (MLCC), 150pF, ±10%, 50V, X7R, ±10%, SMD 0805; Manufacturer: CCTC; Manufacturer Part Number: TCC0805X7R151K500BT
footprint CAP-0805 (0805 (2012M) Capacitor)
pins: 1, 2

## TCC0805X7R152K101DT
designator C?  Capacitance: 1.5nF  (hidden comment: *)
Capacitor, Ceramic (MLCC), 1.5nF, ±10%, 100V, X7R, ±10%, SMD 0805; Manufacturer: CCTC; Manufacturer Part Number: TCC0805X7R152K101DT
footprint CAP-0805 (0805 (2012M) Capacitor)
pins: 1, 2

## TCC0805X7R152K251DT
designator C?  Capacitance: 1.5nF  (hidden comment: *)
Capacitor, Ceramic (MLCC), 1.5nF, ±10%, 250V, X7R, ±10%, SMD 0805; Manufacturer: CCTC; Manufacturer Part Number: TCC0805X7R152K251DT
footprint CAP-0805 (0805 (2012M) Capacitor)
pins: 1, 2

## TCC0805X7R152K500DT
designator C?  Capacitance: 1.5nF  (hidden comment: *)
Capacitor, Ceramic (MLCC), 1.5nF, ±10%, 50V, X7R, ±10%, SMD 0805; Manufacturer: CCTC; Manufacturer Part Number: TCC0805X7R152K500DT
footprint CAP-0805 (0805 (2012M) Capacitor)
pins: 1, 2

## TCC0805X7R153K251FT
designator C?  Capacitance: 15nF  (hidden comment: *)
Capacitor, Ceramic (MLCC), 15nF, ±10%, 250V, X7R, ±10%, SMD 0805; Manufacturer: CCTC; Manufacturer Part Number: TCC0805X7R153K251FT
footprint CAP-0805 (0805 (2012M) Capacitor)
pins: 1, 2

## TCC0805X7R153K500DT
designator C?  Capacitance: 15nF  (hidden comment: *)
Capacitor, Ceramic (MLCC), 15nF, ±10%, 50V, X7R, ±10%, SMD 0805; Manufacturer: CCTC; Manufacturer Part Number: TCC0805X7R153K500DT
footprint CAP-0805 (0805 (2012M) Capacitor)
pins: 1, 2

## TCC0805X7R154K500DT
designator C?  Capacitance: 150nF  (hidden comment: *)
Capacitor, Ceramic (MLCC), 150nF, ±10%, 50V, X7R, ±10%, SMD 0805; Manufacturer: CCTC; Manufacturer Part Number: TCC0805X7R154K500DT
footprint CAP-0805 (0805 (2012M) Capacitor)
pins: 1, 2

## TCC0805X7R181K500BT
designator C?  Capacitance: 180pF  (hidden comment: *)
Capacitor, Ceramic (MLCC), 180pF, ±10%, 50V, X7R, ±10%, SMD 0805; Manufacturer: CCTC; Manufacturer Part Number: TCC0805X7R181K500BT
footprint CAP-0805 (0805 (2012M) Capacitor)
pins: 1, 2

## TCC0805X7R182K101DT
designator C?  Capacitance: 1.8nF  (hidden comment: *)
Capacitor, Ceramic (MLCC), 1.8nF, ±10%, 100V, X7R, ±10%, SMD 0805; Manufacturer: CCTC; Manufacturer Part Number: TCC0805X7R182K101DT
footprint CAP-0805 (0805 (2012M) Capacitor)
pins: 1, 2

## TCC0805X7R182K500DT
designator C?  Capacitance: 1.8nF  (hidden comment: *)
Capacitor, Ceramic (MLCC), 1.8nF, ±10%, 50V, X7R, ±10%, SMD 0805; Manufacturer: CCTC; Manufacturer Part Number: TCC0805X7R182K500DT
footprint CAP-0805 (0805 (2012M) Capacitor)
pins: 1, 2

## TCC0805X7R183K500DT
designator C?  Capacitance: 18nF  (hidden comment: *)
Capacitor, Ceramic (MLCC), 18nF, ±10%, 50V, X7R, ±10%, SMD 0805; Manufacturer: CCTC; Manufacturer Part Number: TCC0805X7R183K500DT
footprint CAP-0805 (0805 (2012M) Capacitor)
pins: 1, 2

## TCC0805X7R184K500DT
designator C?  Capacitance: 180nF  (hidden comment: *)
Capacitor, Ceramic (MLCC), 180nF, ±10%, 50V, X7R, ±10%, SMD 0805; Manufacturer: CCTC; Manufacturer Part Number: TCC0805X7R184K500DT
footprint CAP-0805 (0805 (2012M) Capacitor)
pins: 1, 2

## TCC0805X7R201K500BT
designator C?  Capacitance: 200pF  (hidden comment: *)
Capacitor, Ceramic (MLCC), 200pF, ±10%, 50V, X7R, ±10%, SMD 0805; Manufacturer: CCTC; Manufacturer Part Number: TCC0805X7R201K500BT
footprint CAP-0805 (0805 (2012M) Capacitor)
pins: 1, 2

## TCC0805X7R202K500DT
designator C?  Capacitance: 2nF  (hidden comment: *)
Capacitor, Ceramic (MLCC), 2nF, ±10%, 50V, X7R, ±10%, SMD 0805; Manufacturer: CCTC; Manufacturer Part Number: TCC0805X7R202K500DT
footprint CAP-0805 (0805 (2012M) Capacitor)
pins: 1, 2

## TCC0805X7R203K500DT
designator C?  Capacitance: 20nF  (hidden comment: *)
Capacitor, Ceramic (MLCC), 20nF, ±10%, 50V, X7R, ±10%, SMD 0805; Manufacturer: CCTC; Manufacturer Part Number: TCC0805X7R203K500DT
footprint CAP-0805 (0805 (2012M) Capacitor)
pins: 1, 2

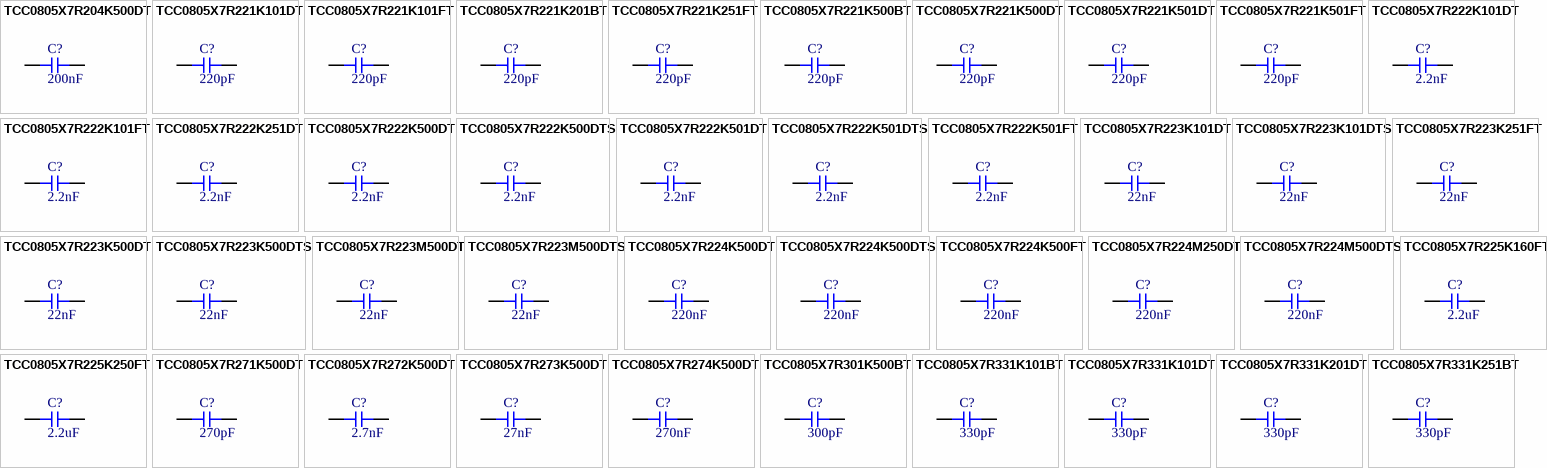
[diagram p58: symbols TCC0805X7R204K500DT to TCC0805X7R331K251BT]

## TCC0805X7R204K500DT
designator C?  Capacitance: 200nF  (hidden comment: *)
Capacitor, Ceramic (MLCC), 200nF, ±10%, 50V, X7R, ±10%, SMD 0805; Manufacturer: CCTC; Manufacturer Part Number: TCC0805X7R204K500DT
footprint CAP-0805 (0805 (2012M) Capacitor)
pins: 1, 2

## TCC0805X7R221K101DT
designator C?  Capacitance: 220pF  (hidden comment: *)
Capacitor, Ceramic (MLCC), 220pF, ±10%, 100V, X7R, ±10%, SMD 0805; Manufacturer: CCTC; Manufacturer Part Number: TCC0805X7R221K101DT
footprint CAP-0805 (0805 (2012M) Capacitor)
pins: 1, 2

## TCC0805X7R221K101FT
designator C?  Capacitance: 220pF  (hidden comment: *)
Capacitor, Ceramic (MLCC), 220pF, ±10%, 100V, X7R, ±10%, SMD 0805; Manufacturer: CCTC; Manufacturer Part Number: TCC0805X7R221K101FT
footprint CAP-0805 (0805 (2012M) Capacitor)
pins: 1, 2

## TCC0805X7R221K201BT
designator C?  Capacitance: 220pF  (hidden comment: *)
Capacitor, Ceramic (MLCC), 220pF, ±10%, 200V, X7R, ±10%, SMD 0805; Manufacturer: CCTC; Manufacturer Part Number: TCC0805X7R221K201BT
footprint CAP-0805 (0805 (2012M) Capacitor)
pins: 1, 2

## TCC0805X7R221K251FT
designator C?  Capacitance: 220pF  (hidden comment: *)
Capacitor, Ceramic (MLCC), 220pF, ±10%, 250V, X7R, ±10%, SMD 0805; Manufacturer: CCTC; Manufacturer Part Number: TCC0805X7R221K251FT
footprint CAP-0805 (0805 (2012M) Capacitor)
pins: 1, 2

## TCC0805X7R221K500BT
designator C?  Capacitance: 220pF  (hidden comment: *)
Capacitor, Ceramic (MLCC), 220pF, ±10%, 50V, X7R, ±10%, SMD 0805; Manufacturer: CCTC; Manufacturer Part Number: TCC0805X7R221K500BT
footprint CAP-0805 (0805 (2012M) Capacitor)
pins: 1, 2

## TCC0805X7R221K500DT
designator C?  Capacitance: 220pF  (hidden comment: *)
Capacitor, Ceramic (MLCC), 220pF, ±10%, 50V, X7R, ±10%, SMD 0805; Manufacturer: CCTC; Manufacturer Part Number: TCC0805X7R221K500DT
footprint CAP-0805 (0805 (2012M) Capacitor)
pins: 1, 2

## TCC0805X7R221K501DT
designator C?  Capacitance: 220pF  (hidden comment: *)
Capacitor, Ceramic (MLCC), 220pF, ±10%, 500V, X7R, ±10%, SMD 0805; Manufacturer: CCTC; Manufacturer Part Number: TCC0805X7R221K501DT
footprint CAP-0805 (0805 (2012M) Capacitor)
pins: 1, 2

## TCC0805X7R221K501FT
designator C?  Capacitance: 220pF  (hidden comment: *)
Capacitor, Ceramic (MLCC), 220pF, ±10%, 500V, X7R, ±10%, SMD 0805; Manufacturer: CCTC; Manufacturer Part Number: TCC0805X7R221K501FT
footprint CAP-0805 (0805 (2012M) Capacitor)
pins: 1, 2

## TCC0805X7R222K101DT
designator C?  Capacitance: 2.2nF  (hidden comment: *)
Capacitor, Ceramic (MLCC), 2.2nF, ±10%, 100V, X7R, ±10%, SMD 0805; Manufacturer: CCTC; Manufacturer Part Number: TCC0805X7R222K101DT
footprint CAP-0805 (0805 (2012M) Capacitor)
pins: 1, 2

## TCC0805X7R222K101FT
designator C?  Capacitance: 2.2nF  (hidden comment: *)
Capacitor, Ceramic (MLCC), 2.2nF, ±10%, 100V, X7R, ±10%, SMD 0805; Manufacturer: CCTC; Manufacturer Part Number: TCC0805X7R222K101FT
footprint CAP-0805 (0805 (2012M) Capacitor)
pins: 1, 2

## TCC0805X7R222K251DT
designator C?  Capacitance: 2.2nF  (hidden comment: *)
Capacitor, Ceramic (MLCC), 2.2nF, ±10%, 250V, X7R, ±10%, SMD 0805; Manufacturer: CCTC; Manufacturer Part Number: TCC0805X7R222K251DT
footprint CAP-0805 (0805 (2012M) Capacitor)
pins: 1, 2

## TCC0805X7R222K500DT
designator C?  Capacitance: 2.2nF  (hidden comment: *)
Capacitor, Ceramic (MLCC), 2.2nF, ±10%, 50V, X7R, ±10%, SMD 0805; Manufacturer: CCTC; Manufacturer Part Number: TCC0805X7R222K500DT
footprint CAP-0805 (0805 (2012M) Capacitor)
pins: 1, 2

## TCC0805X7R222K500DTS
designator C?  Capacitance: 2.2nF  (hidden comment: *)
Capacitor, Ceramic (MLCC), 2.2nF, ±10%, 50V, X7R, ±10%, SMD 0805; Manufacturer: CCTC; Manufacturer Part Number: TCC0805X7R222K500DTS
footprint CAP-0805 (0805 (2012M) Capacitor)
pins: 1, 2

## TCC0805X7R222K501DT
designator C?  Capacitance: 2.2nF  (hidden comment: *)
Capacitor, Ceramic (MLCC), 2.2nF, ±10%, 500V, X7R, ±10%, SMD 0805; Manufacturer: CCTC; Manufacturer Part Number: TCC0805X7R222K501DT
footprint CAP-0805 (0805 (2012M) Capacitor)
pins: 1, 2

## TCC0805X7R222K501DTS
designator C?  Capacitance: 2.2nF  (hidden comment: *)
Capacitor, Ceramic (MLCC), 2.2nF, ±10%, 500V, X7R, ±10%, SMD 0805; Manufacturer: CCTC; Manufacturer Part Number: TCC0805X7R222K501DTS
footprint CAP-0805 (0805 (2012M) Capacitor)
pins: 1, 2

## TCC0805X7R222K501FT
designator C?  Capacitance: 2.2nF  (hidden comment: *)
Capacitor, Ceramic (MLCC), 2.2nF, ±10%, 500V, X7R, ±10%, SMD 0805; Manufacturer: CCTC; Manufacturer Part Number: TCC0805X7R222K501FT
footprint CAP-0805 (0805 (2012M) Capacitor)
pins: 1, 2

## TCC0805X7R223K101DT
designator C?  Capacitance: 22nF  (hidden comment: *)
Capacitor, Ceramic (MLCC), 22nF, ±10%, 100V, X7R, ±10%, SMD 0805; Manufacturer: CCTC; Manufacturer Part Number: TCC0805X7R223K101DT
footprint CAP-0805 (0805 (2012M) Capacitor)
pins: 1, 2

## TCC0805X7R223K101DTS
designator C?  Capacitance: 22nF  (hidden comment: *)
Capacitor, Ceramic (MLCC), 22nF, ±10%, 100V, X7R, ±10%, SMD 0805; Manufacturer: CCTC; Manufacturer Part Number: TCC0805X7R223K101DTS
footprint CAP-0805 (0805 (2012M) Capacitor)
pins: 1, 2

## TCC0805X7R223K251FT
designator C?  Capacitance: 22nF  (hidden comment: *)
Capacitor, Ceramic (MLCC), 22nF, ±10%, 250V, X7R, ±10%, SMD 0805; Manufacturer: CCTC; Manufacturer Part Number: TCC0805X7R223K251FT
footprint CAP-0805 (0805 (2012M) Capacitor)
pins: 1, 2

## TCC0805X7R223K500DT
designator C?  Capacitance: 22nF  (hidden comment: *)
Capacitor, Ceramic (MLCC), 22nF, ±10%, 50V, X7R, ±10%, SMD 0805; Manufacturer: CCTC; Manufacturer Part Number: TCC0805X7R223K500DT
footprint CAP-0805 (0805 (2012M) Capacitor)
pins: 1, 2

## TCC0805X7R223K500DTS
designator C?  Capacitance: 22nF  (hidden comment: *)
Capacitor, Ceramic (MLCC), 22nF, ±10%, 50V, X7R, ±10%, SMD 0805; Manufacturer: CCTC; Manufacturer Part Number: TCC0805X7R223K500DTS
footprint CAP-0805 (0805 (2012M) Capacitor)
pins: 1, 2

## TCC0805X7R223M500DT
designator C?  Capacitance: 22nF  (hidden comment: *)
Capacitor, Ceramic (MLCC), 22nF, ±20%, 50V, X7R, ±20%, SMD 0805; Manufacturer: CCTC; Manufacturer Part Number: TCC0805X7R223M500DT
footprint CAP-0805 (0805 (2012M) Capacitor)
pins: 1, 2

## TCC0805X7R223M500DTS
designator C?  Capacitance: 22nF  (hidden comment: *)
Capacitor, Ceramic (MLCC), 22nF, ±20%, 50V, X7R, ±20%, SMD 0805; Manufacturer: CCTC; Manufacturer Part Number: TCC0805X7R223M500DTS
footprint CAP-0805 (0805 (2012M) Capacitor)
pins: 1, 2

## TCC0805X7R224K500DT
designator C?  Capacitance: 220nF  (hidden comment: *)
Capacitor, Ceramic (MLCC), 220nF, ±10%, 50V, X7R, ±10%, SMD 0805; Manufacturer: CCTC; Manufacturer Part Number: TCC0805X7R224K500DT
footprint CAP-0805 (0805 (2012M) Capacitor)
pins: 1, 2

## TCC0805X7R224K500DTS
designator C?  Capacitance: 220nF  (hidden comment: *)
Capacitor, Ceramic (MLCC), 220nF, ±10%, 50V, X7R, ±10%, SMD 0805; Manufacturer: CCTC; Manufacturer Part Number: TCC0805X7R224K500DTS
footprint CAP-0805 (0805 (2012M) Capacitor)
pins: 1, 2

## TCC0805X7R224K500FT
designator C?  Capacitance: 220nF  (hidden comment: *)
Capacitor, Ceramic (MLCC), 220nF, ±10%, 50V, X7R, ±10%, SMD 0805; Manufacturer: CCTC; Manufacturer Part Number: TCC0805X7R224K500FT
footprint CAP-0805 (0805 (2012M) Capacitor)
pins: 1, 2

## TCC0805X7R224M250DT
designator C?  Capacitance: 220nF  (hidden comment: *)
Capacitor, Ceramic (MLCC), 220nF, ±20%, 25V, X7R, ±20%, SMD 0805; Manufacturer: CCTC; Manufacturer Part Number: TCC0805X7R224M250DT
footprint CAP-0805 (0805 (2012M) Capacitor)
pins: 1, 2

## TCC0805X7R224M500DTS
designator C?  Capacitance: 220nF  (hidden comment: *)
Capacitor, Ceramic (MLCC), 220nF, ±20%, 50V, X7R, ±20%, SMD 0805; Manufacturer: CCTC; Manufacturer Part Number: TCC0805X7R224M500DTS
footprint CAP-0805 (0805 (2012M) Capacitor)
pins: 1, 2

## TCC0805X7R225K160FT
designator C?  Capacitance: 2.2uF  (hidden comment: *)
Capacitor, Ceramic (MLCC), 2.2uF, ±10%, 16V, X7R, ±10%, SMD 0805; Manufacturer: CCTC; Manufacturer Part Number: TCC0805X7R225K160FT
footprint CAP-0805 (0805 (2012M) Capacitor)
pins: 1, 2

## TCC0805X7R225K250FT
designator C?  Capacitance: 2.2uF  (hidden comment: *)
Capacitor, Ceramic (MLCC), 2.2uF, ±10%, 25V, X7R, ±10%, SMD 0805; Manufacturer: CCTC; Manufacturer Part Number: TCC0805X7R225K250FT
footprint CAP-0805 (0805 (2012M) Capacitor)
pins: 1, 2

## TCC0805X7R271K500DT
designator C?  Capacitance: 270pF  (hidden comment: *)
Capacitor, Ceramic (MLCC), 270pF, ±10%, 50V, X7R, ±10%, SMD 0805; Manufacturer: CCTC; Manufacturer Part Number: TCC0805X7R271K500DT
footprint CAP-0805 (0805 (2012M) Capacitor)
pins: 1, 2

## TCC0805X7R272K500DT
designator C?  Capacitance: 2.7nF  (hidden comment: *)
Capacitor, Ceramic (MLCC), 2.7nF, ±10%, 50V, X7R, ±10%, SMD 0805; Manufacturer: CCTC; Manufacturer Part Number: TCC0805X7R272K500DT
footprint CAP-0805 (0805 (2012M) Capacitor)
pins: 1, 2

## TCC0805X7R273K500DT
designator C?  Capacitance: 27nF  (hidden comment: *)
Capacitor, Ceramic (MLCC), 27nF, ±10%, 50V, X7R, ±10%, SMD 0805; Manufacturer: CCTC; Manufacturer Part Number: TCC0805X7R273K500DT
footprint CAP-0805 (0805 (2012M) Capacitor)
pins: 1, 2

## TCC0805X7R274K500DT
designator C?  Capacitance: 270nF  (hidden comment: *)
Capacitor, Ceramic (MLCC), 270nF, ±10%, 50V, X7R, ±10%, SMD 0805; Manufacturer: CCTC; Manufacturer Part Number: TCC0805X7R274K500DT
footprint CAP-0805 (0805 (2012M) Capacitor)
pins: 1, 2

## TCC0805X7R301K500BT
designator C?  Capacitance: 300pF  (hidden comment: *)
Capacitor, Ceramic (MLCC), 300pF, ±10%, 50V, X7R, ±10%, SMD 0805; Manufacturer: CCTC; Manufacturer Part Number: TCC0805X7R301K500BT
footprint CAP-0805 (0805 (2012M) Capacitor)
pins: 1, 2

## TCC0805X7R331K101BT
designator C?  Capacitance: 330pF  (hidden comment: *)
Capacitor, Ceramic (MLCC), 330pF, ±10%, 100V, X7R, ±10%, SMD 0805; Manufacturer: CCTC; Manufacturer Part Number: TCC0805X7R331K101BT
footprint CAP-0805 (0805 (2012M) Capacitor)
pins: 1, 2

## TCC0805X7R331K101DT
designator C?  Capacitance: 330pF  (hidden comment: *)
Capacitor, Ceramic (MLCC), 330pF, ±10%, 100V, X7R, ±10%, SMD 0805; Manufacturer: CCTC; Manufacturer Part Number: TCC0805X7R331K101DT
footprint CAP-0805 (0805 (2012M) Capacitor)
pins: 1, 2

## TCC0805X7R331K201DT
designator C?  Capacitance: 330pF  (hidden comment: *)
Capacitor, Ceramic (MLCC), 330pF, ±10%, 200V, X7R, ±10%, SMD 0805; Manufacturer: CCTC; Manufacturer Part Number: TCC0805X7R331K201DT
footprint CAP-0805 (0805 (2012M) Capacitor)
pins: 1, 2

## TCC0805X7R331K251BT
designator C?  Capacitance: 330pF  (hidden comment: *)
Capacitor, Ceramic (MLCC), 330pF, ±10%, 250V, X7R, ±10%, SMD 0805; Manufacturer: CCTC; Manufacturer Part Number: TCC0805X7R331K251BT
footprint CAP-0805 (0805 (2012M) Capacitor)
pins: 1, 2

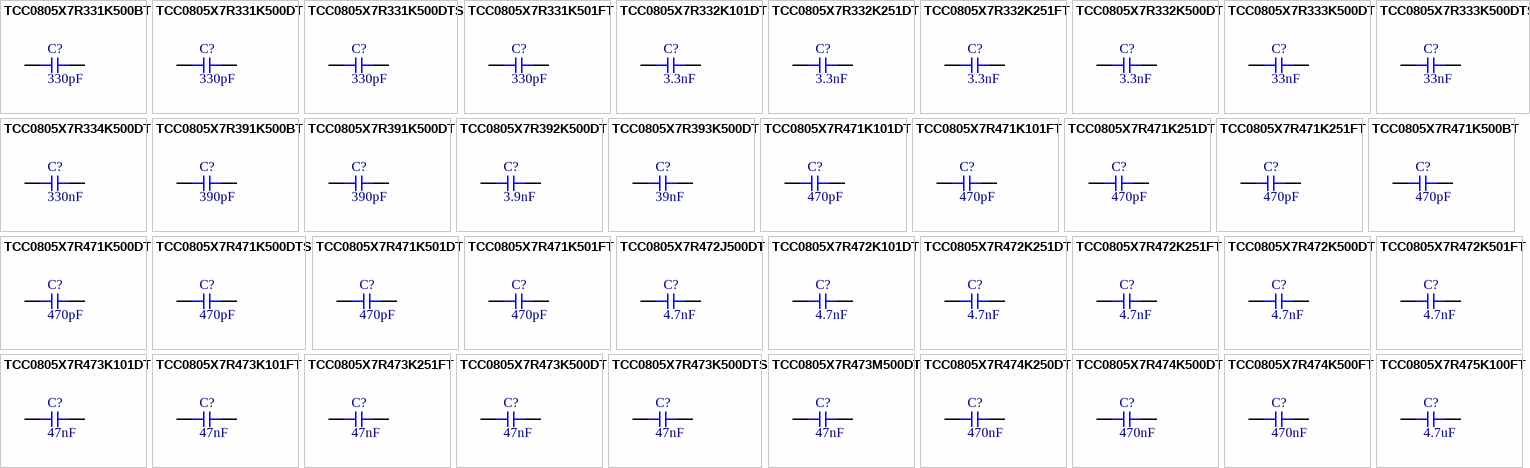
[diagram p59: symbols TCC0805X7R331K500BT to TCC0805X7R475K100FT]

## TCC0805X7R331K500BT
designator C?  Capacitance: 330pF  (hidden comment: *)
Capacitor, Ceramic (MLCC), 330pF, ±10%, 50V, X7R, ±10%, SMD 0805; Manufacturer: CCTC; Manufacturer Part Number: TCC0805X7R331K500BT
footprint CAP-0805 (0805 (2012M) Capacitor)
pins: 1, 2

## TCC0805X7R331K500DT
designator C?  Capacitance: 330pF  (hidden comment: *)
Capacitor, Ceramic (MLCC), 330pF, ±10%, 50V, X7R, ±10%, SMD 0805; Manufacturer: CCTC; Manufacturer Part Number: TCC0805X7R331K500DT
footprint CAP-0805 (0805 (2012M) Capacitor)
pins: 1, 2

## TCC0805X7R331K500DTS
designator C?  Capacitance: 330pF  (hidden comment: *)
Capacitor, Ceramic (MLCC), 330pF, ±10%, 50V, X7R, ±10%, SMD 0805; Manufacturer: CCTC; Manufacturer Part Number: TCC0805X7R331K500DTS
footprint CAP-0805 (0805 (2012M) Capacitor)
pins: 1, 2

## TCC0805X7R331K501FT
designator C?  Capacitance: 330pF  (hidden comment: *)
Capacitor, Ceramic (MLCC), 330pF, ±10%, 500V, X7R, ±10%, SMD 0805; Manufacturer: CCTC; Manufacturer Part Number: TCC0805X7R331K501FT
footprint CAP-0805 (0805 (2012M) Capacitor)
pins: 1, 2

## TCC0805X7R332K101DT
designator C?  Capacitance: 3.3nF  (hidden comment: *)
Capacitor, Ceramic (MLCC), 3.3nF, ±10%, 100V, X7R, ±10%, SMD 0805; Manufacturer: CCTC; Manufacturer Part Number: TCC0805X7R332K101DT
footprint CAP-0805 (0805 (2012M) Capacitor)
pins: 1, 2

## TCC0805X7R332K251DT
designator C?  Capacitance: 3.3nF  (hidden comment: *)
Capacitor, Ceramic (MLCC), 3.3nF, ±10%, 250V, X7R, ±10%, SMD 0805; Manufacturer: CCTC; Manufacturer Part Number: TCC0805X7R332K251DT
footprint CAP-0805 (0805 (2012M) Capacitor)
pins: 1, 2

## TCC0805X7R332K251FT
designator C?  Capacitance: 3.3nF  (hidden comment: *)
Capacitor, Ceramic (MLCC), 3.3nF, ±10%, 250V, X7R, ±10%, SMD 0805; Manufacturer: CCTC; Manufacturer Part Number: TCC0805X7R332K251FT
footprint CAP-0805 (0805 (2012M) Capacitor)
pins: 1, 2

## TCC0805X7R332K500DT
designator C?  Capacitance: 3.3nF  (hidden comment: *)
Capacitor, Ceramic (MLCC), 3.3nF, ±10%, 50V, X7R, ±10%, SMD 0805; Manufacturer: CCTC; Manufacturer Part Number: TCC0805X7R332K500DT
footprint CAP-0805 (0805 (2012M) Capacitor)
pins: 1, 2

## TCC0805X7R333K500DT
designator C?  Capacitance: 33nF  (hidden comment: *)
Capacitor, Ceramic (MLCC), 33nF, ±10%, 50V, X7R, ±10%, SMD 0805; Manufacturer: CCTC; Manufacturer Part Number: TCC0805X7R333K500DT
footprint CAP-0805 (0805 (2012M) Capacitor)
pins: 1, 2

## TCC0805X7R333K500DTS
designator C?  Capacitance: 33nF  (hidden comment: *)
Capacitor, Ceramic (MLCC), 33nF, ±10%, 50V, X7R, ±10%, SMD 0805; Manufacturer: CCTC; Manufacturer Part Number: TCC0805X7R333K500DTS
footprint CAP-0805 (0805 (2012M) Capacitor)
pins: 1, 2

## TCC0805X7R334K500DT
designator C?  Capacitance: 330nF  (hidden comment: *)
Capacitor, Ceramic (MLCC), 330nF, ±10%, 50V, X7R, ±10%, SMD 0805; Manufacturer: CCTC; Manufacturer Part Number: TCC0805X7R334K500DT
footprint CAP-0805 (0805 (2012M) Capacitor)
pins: 1, 2

## TCC0805X7R391K500BT
designator C?  Capacitance: 390pF  (hidden comment: *)
Capacitor, Ceramic (MLCC), 390pF, ±10%, 50V, X7R, ±10%, SMD 0805; Manufacturer: CCTC; Manufacturer Part Number: TCC0805X7R391K500BT
footprint CAP-0805 (0805 (2012M) Capacitor)
pins: 1, 2

## TCC0805X7R391K500DT
designator C?  Capacitance: 390pF  (hidden comment: *)
Capacitor, Ceramic (MLCC), 390pF, ±10%, 50V, X7R, ±10%, SMD 0805; Manufacturer: CCTC; Manufacturer Part Number: TCC0805X7R391K500DT
footprint CAP-0805 (0805 (2012M) Capacitor)
pins: 1, 2

## TCC0805X7R392K500DT
designator C?  Capacitance: 3.9nF  (hidden comment: *)
Capacitor, Ceramic (MLCC), 3.9nF, ±10%, 50V, X7R, ±10%, SMD 0805; Manufacturer: CCTC; Manufacturer Part Number: TCC0805X7R392K500DT
footprint CAP-0805 (0805 (2012M) Capacitor)
pins: 1, 2

## TCC0805X7R393K500DT
designator C?  Capacitance: 39nF  (hidden comment: *)
Capacitor, Ceramic (MLCC), 39nF, ±10%, 50V, X7R, ±10%, SMD 0805; Manufacturer: CCTC; Manufacturer Part Number: TCC0805X7R393K500DT
footprint CAP-0805 (0805 (2012M) Capacitor)
pins: 1, 2

## TCC0805X7R471K101DT
designator C?  Capacitance: 470pF  (hidden comment: *)
Capacitor, Ceramic (MLCC), 470pF, ±10%, 100V, X7R, ±10%, SMD 0805; Manufacturer: CCTC; Manufacturer Part Number: TCC0805X7R471K101DT
footprint CAP-0805 (0805 (2012M) Capacitor)
pins: 1, 2

## TCC0805X7R471K101FT
designator C?  Capacitance: 470pF  (hidden comment: *)
Capacitor, Ceramic (MLCC), 470pF, ±10%, 100V, X7R, ±10%, SMD 0805; Manufacturer: CCTC; Manufacturer Part Number: TCC0805X7R471K101FT
footprint CAP-0805 (0805 (2012M) Capacitor)
pins: 1, 2

## TCC0805X7R471K251DT
designator C?  Capacitance: 470pF  (hidden comment: *)
Capacitor, Ceramic (MLCC), 470pF, ±10%, 250V, X7R, ±10%, SMD 0805; Manufacturer: CCTC; Manufacturer Part Number: TCC0805X7R471K251DT
footprint CAP-0805 (0805 (2012M) Capacitor)
pins: 1, 2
